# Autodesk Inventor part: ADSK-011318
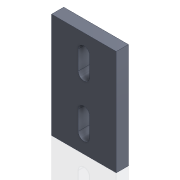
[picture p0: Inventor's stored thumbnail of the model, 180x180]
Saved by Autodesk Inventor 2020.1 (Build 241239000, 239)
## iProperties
Created: 1999-12
Part Number: ADSK-011318
Document SubType Name: Modeling
Designer: sspink
Material: Pearson Stainless Steel
Density: 8.03 g/cm^3
Appearance: Pearson-Stainless
Mass: 290.363 g
Surface Area: 112.431 cm^2
Volume: 36.1598 cm^3
Control State: 0
Master: False
Checked Out: False
Shininess: 57.0
Length Units: 11269
Angle Units: 11279
Time Units: 11290
Mass Units: 11283
Length Display Precision: 3
Angle Display Precision: 2
Compacted: True
Cutlength: 3.25
Material Desc: FLAT,S/S,0.375 X 2.00
Material_number: A084622
Dimensions: 50,8x82,6x9,5 mm
Mass: 0,29 kg
DocNumber: ADSK-011318.ipt
Folder: 01 - Themengebiete\Simplification\01 - Packaging machine\
VDS_Category: 3D Komponenten
Density: 8.03
Volumn: 35.22979967814412
Area: 111.60038005902123
PropertySet Name: Model Information
Author: sspink
Revision Number: -
Title: base plate
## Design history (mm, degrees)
node "Solide1"
  node "Extrusion1" dims "d4" = 9.525, "d5" = 0
  node "Extrusion2" dims "d13" = 9.525, "d14" = 0
sketch "Sketch2"
  geometry: L1 (-52.298, -66.675)-(-52.298, 15.875) reference; L2 (-1.498, -66.675)-(-52.298, -66.675) reference; L3 (-22.398, 2.6)-(-31.398, 2.6); L4 (-31.398, 2.6)-(-31.398, -12.4); L5 (-31.398, -12.4)-(-22.398, -12.4); L6 (-22.398, -12.4)-(-22.398, 2.6); L7 (-22.398, -38.4)-(-31.398, -38.4); L8 (-31.398, -38.4)-(-31.398, -53.4); L9 (-31.398, -53.4)-(-22.398, -53.4); L10 (-22.398, -53.4)-(-22.398, -38.4); L11 (-26.898, 2.6)-(-26.898, -12.4); L12 (-26.898, -38.4)-(-26.898, -53.4); L13 (-26.898, -4.9)-(-26.898, -45.9); A1 r 4.5 centre (-26.898, 2.6) between (-22.398, 2.6) and (-31.398, 2.6); A2 r 4.5 centre (-26.898, -12.4) between (-31.398, -12.4) and (-22.398, -12.4); A3 r 4.5 centre (-26.898, -38.4) between (-22.398, -38.4) and (-31.398, -38.4); A4 r 4.5 centre (-26.898, -53.4) between (-31.398, -53.4) and (-22.398, -53.4); 6 further points
  constraints: 22 end point, 9 point on circle, 7 midpoint, 4 centre point, 4 parallel, 4 tangent, 3 perpendicular, 2 horizontal, 2 vertical alignment, 1 collinear, 1 equal radius, 1 horizontal alignment, 1 vertical
  dimensions: "d16" = 41 distance of L13.start L13.end; "d17" = 9 distance between parallel lines of L4 L6; "d18" = 15 distance of L3.end L4.end; "d19" = 15 distance of L7.end L8.end (= d18)
workpoint "Arbeitspunkt1"
workpoint "Arbeitspunkt2"
workaxis "Arbeitsachse1"
workaxis "Arbeitsachse2"
node "Corps solides"
node "Corps surfaciques"
sketch "Sketch1"
  geometry: L1 (-52.298, 15.875)-(-1.498, 15.875); L2 (-1.498, -66.675)-(-52.298, -66.675) reference; L3 (-52.298, -66.675)-(-52.298, 15.875) reference; L4 (-1.498, -66.675)-(-1.498, 15.875)
  constraints: 8 end point, 2 horizontal, 2 parallel, 1 vertical
  dimensions: "d3" = 50.8 distance of L2.start L2.end; "d15" = 82.55 distance of L2.end L1.start
